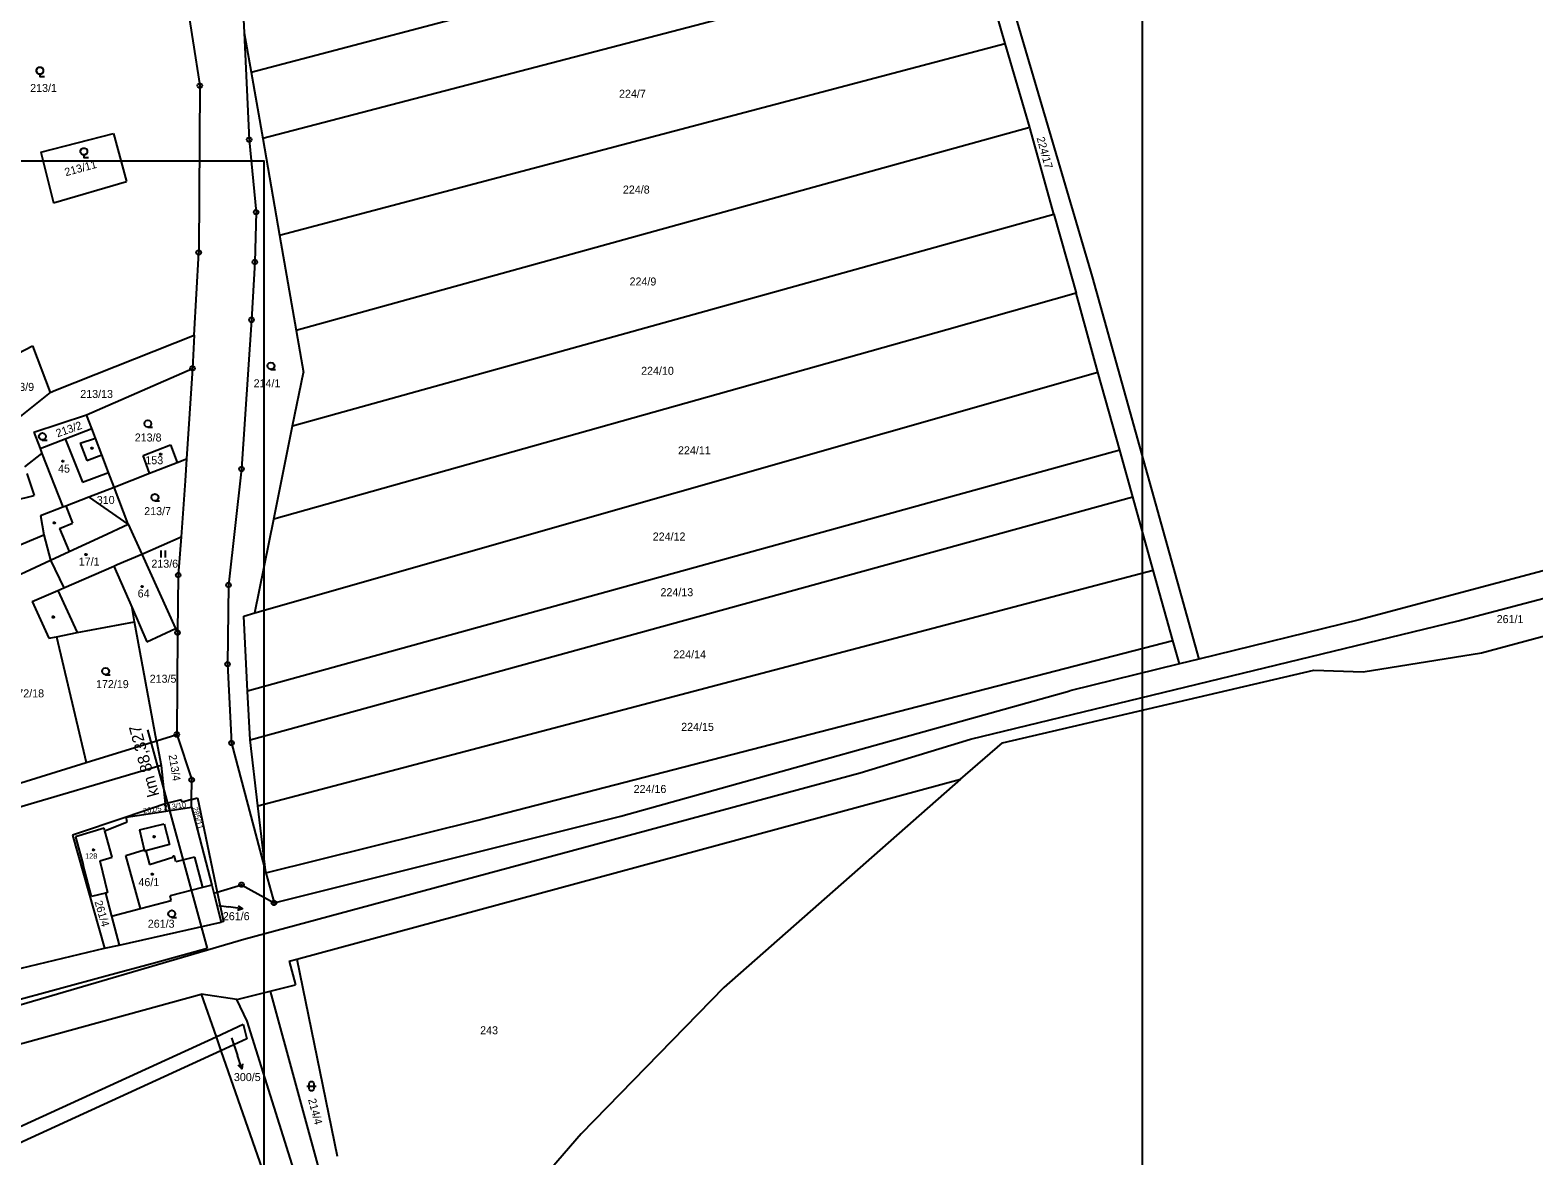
# Model space of a CAD drawing. Extents: x -780000 to -777378, y -1011169 to -1009297.
# Drawn here: x -778986.4 to -778666.9, y -1010479.3 to -1010240.1 of the extents above; entities that cross this region are included whole.
import ezdxf

# ---------------------------------------------------------------- set-up
doc = ezdxf.new("R2010")
doc.units = 0
for name, color, linetype in [('Default', 7, 'Continuous'), ('KLADY_ZMVM', 7, 'Continuous'), ('KN_HRANICE', 7, 'Continuous'), ('KN_KULTURY', 7, 'Continuous'), ('KN_PARCELY', 7, 'Continuous'), ('KN_SLUCKY', 7, 'Continuous'), ('KN_VEDENI', 7, 'Continuous'), ('LEGENDA', 7, 'Continuous'), ('staničení', 7, 'Continuous'), ('Železniční svršek', 7, 'Continuous')]:
    doc.layers.add(name, color=color, linetype=linetype)

# ---------------------------------------------------------------- blocks, each defined once
blk = doc.blocks.new('304')
at = {"layer": 'Default'}
blk.add_lwpolyline([(0, 0), (-0.38, 0.1), (-0.65, 0.37), (-0.75, 0.74), (-0.65, 1.11), (-0.38, 1.38), (-0.01, 1.48), (0.36, 1.38), (0.63, 1.11), (0.73, 0.73), (0.63, 0.35), (0.36, 0.08), (-0.02, -0.02), (0.98, -0.02)], dxfattribs=at)
blk = doc.blocks.new('305')
at = {"layer": 'Default'}
blk.add_lwpolyline([(0, 0.53), (-0.19, 0.53), (-0.53, 0.72), (-0.72, 1.06), (-0.72, 1.45), (-0.53, 1.79), (-0.19, 1.98), (0.2, 1.98), (0.54, 1.79), (0.73, 1.45), (0.73, 1.06), (0.54, 0.72), (0.2, 0.53), (0.01, 0.53), (0.01, 0), (1.01, 0)], dxfattribs=at)
blk = doc.blocks.new('306')
at = {"layer": 'Default'}
for p, q in [((-0.5, 1.5), (-0.5, 0)), ((0.5, 0), (0.5, 1.5))]:
    blk.add_line(p, q, dxfattribs=at)
blk = doc.blocks.new('316')
at = {"layer": 'Default'}
for points in [[(-1, 1), (0.27, 1), (1, 1)], [(-0.5, 1.5), (-0.4, 1.79), (-0.15, 1.97), (0.16, 1.97), (0.41, 1.79), (0.51, 1.5), (0.51, 0.5), (0.41, 0.21), (0.16, 0.03), (-0.15, 0.03), (-0.4, 0.21), (-0.5, 0.5), (-0.5, 1.5)]]:
    blk.add_lwpolyline(points, dxfattribs=at)
blk = doc.blocks.new('10292')
at = {"layer": 'Default'}
blk.add_line((0, 3), (0, 0), dxfattribs=at)
blk.add_lwpolyline([(-0.5, 2), (0, 3), (0.5, 2)], dxfattribs=at)
blk = doc.blocks.new('402')
at = {"layer": 'Default'}
blk.add_lwpolyline([(0.09, 0.15), (0.18, 0), (0.09, -0.15), (-0.09, -0.15), (-0.18, 0), (-0.09, 0.15), (0.09, 0.15)], dxfattribs=at)
blk = doc.blocks.new('105')
at = {"layer": 'Default'}
blk.add_line((-0.12, 0), (0.12, 0), dxfattribs=at)
blk.add_lwpolyline([(0.15, 0.48), (0.4, 0.3), (0.5, 0.01), (0.4, -0.28), (0.15, -0.46), (-0.16, -0.46), (-0.41, -0.28), (-0.51, 0.01), (-0.41, 0.3), (-0.16, 0.48), (0.15, 0.48)], dxfattribs=at)

msp = doc.modelspace()

# ---------------------------------------------------------------- linework, layer by layer
at = {"layer": 'KLADY_ZMVM'}
msp.add_lwpolyline([(-779108.78, -1010500), (-778750, -1010500), (-778750, -1010000)], dxfattribs=at)
at = {"layer": 'KN_HRANICE'}
for p, q in [((-778810.44, -1010123.41), (-778760.75, -1010292.49)), ((-778939.44, -1010249.05), (-778789, -1010209.36)), ((-778784.9, -1010223.38), (-778936.98, -1010263.15)), ((-778779.19, -1010242.93), (-778784.9, -1010223.38)), ((-778953.35, -1010232.46), (-778950.34, -1010251.89)), ((-778941.17, -1010234.88), (-778940.9, -1010240.67)), ((-778940.9, -1010240.67), (-778939.84, -1010263.37)), ((-778940.9, -1010240.67), (-778939.44, -1010249.05)), ((-778933.41, -1010283.65), (-778779.19, -1010242.93)), ((-778773.96, -1010260.81), (-778779.19, -1010242.93)), ((-778939.44, -1010249.05), (-778936.98, -1010263.15)), ((-778984.11, -1010266.01), (-778968.66, -1010262.03)), ((-778968.66, -1010262.03), (-778965.93, -1010272.29)), ((-778773.96, -1010260.81), (-778929.88, -1010303.92)), ((-778773.89, -1010261.06), (-778773.96, -1010260.81)), ((-778768.84, -1010279.18), (-778773.89, -1010261.06)), ((-778939.84, -1010263.37), (-778938.39, -1010278.77)), ((-778936.98, -1010263.15), (-778933.41, -1010283.65)), ((-778984.11, -1010266.01), (-778981.47, -1010276.78)), ((-778981.47, -1010276.78), (-778965.93, -1010272.29)), ((-778938.39, -1010278.77), (-778938.64, -1010289.39)), ((-778930.63, -1010324.14), (-778768.84, -1010279.18)), ((-778768.84, -1010279.18), (-778764.72, -1010293.95)), ((-778933.41, -1010283.65), (-778929.88, -1010303.92)), ((-778951.52, -1010304.9), (-778950.58, -1010287.37)), ((-778938.64, -1010289.39), (-778939.36, -1010301.65)), ((-778764.72, -1010293.95), (-778764.15, -1010296.01)), ((-778760.75, -1010292.49), (-778738.09, -1010373.73)), ((-778764.15, -1010296.01), (-778791.6, -1010303.74)), ((-778759.49, -1010312.74), (-778764.15, -1010296.01)), ((-778939.36, -1010301.65), (-778941.47, -1010333.34)), ((-778980.98, -1010316.61), (-778951.52, -1010304.9)), ((-778951.52, -1010304.9), (-778951.89, -1010311.98)), ((-778791.6, -1010303.74), (-778934.65, -1010344)), ((-778929.88, -1010303.92), (-778928.34, -1010312.81)), ((-778994.79, -1010311.83), (-778985.9, -1010307.16)), ((-778985.9, -1010307.16), (-778982.17, -1010317.08)), ((-778974.4, -1010321.81), (-778951.89, -1010311.98)), ((-778951.89, -1010311.98), (-778953.14, -1010331.19)), ((-778938.68, -1010363.9), (-778759.49, -1010312.74)), ((-778930.63, -1010324.14), (-778928.34, -1010312.81)), ((-778754.87, -1010329.33), (-778759.49, -1010312.74)), ((-778982.17, -1010317.08), (-778991.02, -1010324.17)), ((-778982.17, -1010317.08), (-778980.98, -1010316.61)), ((-778985.64, -1010325.53), (-778974.4, -1010321.81)), ((-778973.3, -1010324.71), (-778974.4, -1010321.81)), ((-778985.64, -1010325.53), (-778984.3, -1010328.99)), ((-778978.98, -1010326.92), (-778973.3, -1010324.71)), ((-778972.52, -1010326.77), (-778973.3, -1010324.71)), ((-778934.65, -1010344), (-778930.63, -1010324.14)), ((-778984.3, -1010328.99), (-778978.98, -1010326.92)), ((-778984.3, -1010328.99), (-778983.88, -1010330.06)), ((-778971.16, -1010330.34), (-778972.52, -1010326.77)), ((-778962.38, -1010330.47), (-778956.54, -1010328.23)), ((-778956.54, -1010328.23), (-778955.13, -1010331.96)), ((-778987.54, -1010332.88), (-778983.88, -1010330.06)), ((-778983.88, -1010330.06), (-778979.48, -1010341.4)), ((-778969.74, -1010334.07), (-778971.16, -1010330.34)), ((-778961.01, -1010334.24), (-778962.38, -1010330.47)), ((-778961.01, -1010334.24), (-778955.13, -1010331.96)), ((-778955.13, -1010331.96), (-778953.14, -1010331.19)), ((-778953.14, -1010331.19), (-778953.44, -1010335.87)), ((-778754.87, -1010329.33), (-778940.18, -1010380.55)), ((-778752.11, -1010339.25), (-778754.87, -1010329.33)), ((-778968.56, -1010337.17), (-778969.74, -1010334.07)), ((-778968.56, -1010337.17), (-778961.01, -1010334.24)), ((-778941.47, -1010333.34), (-778944.25, -1010358.02)), ((-778973.94, -1010339.25), (-778968.56, -1010337.17)), ((-778965.56, -1010345.08), (-778968.56, -1010337.17)), ((-778953.44, -1010335.87), (-778954.32, -1010347.77)), ((-778984.19, -1010343.23), (-778979.48, -1010341.4)), ((-778979.48, -1010341.4), (-778978.84, -1010341.15)), ((-778978.84, -1010341.15), (-778977.19, -1010340.51)), ((-778977.19, -1010340.51), (-778973.94, -1010339.25)), ((-778965.56, -1010345.08), (-778973.94, -1010339.25)), ((-778939.67, -1010390.9), (-778752.11, -1010339.25)), ((-778747.77, -1010354.85), (-778752.11, -1010339.25)), ((-778984.19, -1010343.23), (-778983.47, -1010347.31)), ((-778965.56, -1010345.08), (-778962.69, -1010351.41)), ((-778938.68, -1010363.9), (-778934.65, -1010344)), ((-778983.47, -1010347.31), (-778982.04, -1010352.73)), ((-778962.69, -1010351.41), (-778954.32, -1010347.77)), ((-778954.32, -1010347.77), (-778954.92, -1010355.9)), ((-778967.89, -1010353.67), (-778962.69, -1010351.41)), ((-778962.69, -1010351.41), (-778955.49, -1010367.27)), ((-778650.77, -1010351.2), (-778703.98, -1010365.37)), ((-778997.87, -1010360.08), (-778982.04, -1010352.73)), ((-778982.04, -1010352.73), (-778979.24, -1010358.61)), ((-778979.24, -1010358.61), (-778968.59, -1010353.97)), ((-778968.59, -1010353.97), (-778967.89, -1010353.67)), ((-778954.92, -1010355.9), (-778955.1, -1010368.13)), ((-778937.98, -1010404.92), (-778747.77, -1010354.85)), ((-778743.6, -1010369.82), (-778747.77, -1010354.85)), ((-778985.96, -1010361.53), (-778980.51, -1010359.16)), ((-778980.51, -1010359.16), (-778979.24, -1010358.61)), ((-778944.25, -1010358.02), (-778944.43, -1010374.8)), ((-778985.96, -1010361.53), (-778982.41, -1010369.32)), ((-778964.75, -1010362.86), (-778961.63, -1010370.1)), ((-778964.2, -1010365.84), (-778964.75, -1010362.86)), ((-778940.96, -1010364.6), (-778938.68, -1010363.9)), ((-778976.43, -1010368.12), (-778964.2, -1010365.84)), ((-778959.52, -1010391.1), (-778964.2, -1010365.84)), ((-778961.63, -1010370.1), (-778955.49, -1010367.27)), ((-778955.49, -1010367.27), (-778955.1, -1010368.13)), ((-778940.18, -1010380.55), (-778940.96, -1010364.6)), ((-778703.98, -1010365.37), (-778738.09, -1010373.73)), ((-778678, -1010372.43), (-778652.28, -1010365.5)), ((-778982.41, -1010369.32), (-778980.82, -1010369)), ((-778980.82, -1010369), (-778976.43, -1010368.12)), ((-778980.82, -1010369), (-778974.46, -1010395.73)), ((-778955.1, -1010368.13), (-778955.22, -1010389.77)), ((-778891.25, -1010407.94), (-778743.6, -1010369.82)), ((-778742.19, -1010374.76), (-778743.6, -1010369.82)), ((-778738.09, -1010373.73), (-778742.19, -1010374.76)), ((-778703.11, -1010376.44), (-778678, -1010372.43)), ((-778944.43, -1010374.8), (-778943.59, -1010391.58)), ((-778779.77, -1010391.5), (-778713.61, -1010376.07)), ((-778742.19, -1010374.76), (-778765.47, -1010380.48)), ((-778713.61, -1010376.07), (-778703.11, -1010376.44)), ((-778939.67, -1010390.9), (-778940.18, -1010380.55)), ((-778860.91, -1010407.13), (-778765.47, -1010380.48)), ((-778959.52, -1010391.1), (-778955.22, -1010389.77)), ((-778955.22, -1010389.77), (-778952.07, -1010399.39)), ((-778974.46, -1010395.73), (-778959.52, -1010391.1)), ((-778959.52, -1010391.1), (-778958.54, -1010396.31)), ((-778943.59, -1010391.58), (-778936.31, -1010419.18)), ((-778937.98, -1010404.92), (-778939.67, -1010390.9)), ((-778788.69, -1010399.25), (-778779.77, -1010391.5)), ((-778988.37, -1010400.03), (-778974.46, -1010395.73)), ((-778958.54, -1010396.31), (-779043.02, -1010421.24)), ((-778958.54, -1010396.31), (-778957.7, -1010404.52)), ((-778952.08, -1010403.6), (-778952.07, -1010399.39)), ((-778929.7, -1010437.49), (-778788.69, -1010399.25)), ((-778788.69, -1010399.25), (-778838.99, -1010443.52)), ((-778957.7, -1010404.52), (-778966, -1010407.32)), ((-778954.34, -1010403.64), (-778957.7, -1010404.52)), ((-778957.7, -1010404.52), (-778957.55, -1010406.02)), ((-778957.55, -1010406.02), (-778952.09, -1010405.18)), ((-778954.03, -1010404.17), (-778954.34, -1010403.64)), ((-778952.08, -1010403.6), (-778954.03, -1010404.17)), ((-778952.09, -1010405.18), (-778952.08, -1010403.6)), ((-778952.09, -1010405.18), (-778947.8, -1010421.79)), ((-778952.08, -1010403.6), (-778950.86, -1010403.24)), ((-778950.86, -1010403.24), (-778946.64, -1010423.24)), ((-778936.31, -1010419.18), (-778937.98, -1010404.92)), ((-778966, -1010407.32), (-778977.43, -1010411.17)), ((-778970.52, -1010410.2), (-778965.76, -1010408.34)), ((-778966, -1010407.32), (-778957.55, -1010406.02)), ((-778965.76, -1010408.34), (-778966, -1010407.32)), ((-778936.31, -1010419.18), (-778891.25, -1010407.94)), ((-778934.57, -1010425.53), (-778860.91, -1010407.13)), ((-778977.43, -1010411.17), (-778970.59, -1010435.19)), ((-778970.66, -1010409.66), (-778976.79, -1010411.48)), ((-778976.79, -1010411.48), (-778975.16, -1010417.48)), ((-778970.52, -1010410.2), (-778970.66, -1010409.66)), ((-778968.98, -1010415.79), (-778970.52, -1010410.2)), ((-778973.38, -1010424.16), (-778975.16, -1010417.48)), ((-778971.61, -1010416.57), (-778968.98, -1010415.79)), ((-778971.61, -1010416.57), (-778969.93, -1010423.36)), ((-778947.8, -1010421.79), (-778949.74, -1010422.28)), ((-778947.8, -1010421.79), (-778947.37, -1010423.47)), ((-778946.64, -1010423.24), (-778941.48, -1010421.68)), ((-778941.48, -1010421.68), (-778934.57, -1010425.53)), ((-778936.31, -1010419.18), (-778934.57, -1010425.53)), ((-778970.41, -1010423.47), (-778973.38, -1010424.16)), ((-778969.93, -1010423.36), (-778970.41, -1010423.47)), ((-778970.41, -1010423.47), (-778969.13, -1010428.34)), ((-778962.94, -1010426.72), (-778956.41, -1010425.01)), ((-778949.74, -1010422.28), (-778956.63, -1010424.04)), ((-778956.41, -1010425.01), (-778956.63, -1010424.04)), ((-778947.37, -1010423.47), (-778946.64, -1010423.24)), ((-778947.37, -1010423.47), (-778945.78, -1010429.62)), ((-778946.64, -1010423.24), (-778945.31, -1010429.51)), ((-778969.13, -1010428.34), (-778962.94, -1010426.72)), ((-778969.13, -1010428.34), (-778967.51, -1010434.5)), ((-778967.51, -1010434.5), (-778945.78, -1010429.62)), ((-778945.31, -1010429.51), (-778945.78, -1010429.62)), ((-778970.59, -1010435.19), (-778967.51, -1010434.5)), ((-779030.17, -1010449.35), (-778970.59, -1010435.19)), ((-778931.37, -1010437.94), (-778929.7, -1010437.49)), ((-778929.7, -1010437.49), (-778921.17, -1010479.33)), ((-778931.37, -1010437.94), (-778930.03, -1010442.98)), ((-778935.36, -1010444.3), (-778930.03, -1010442.98)), ((-778838.99, -1010443.52), (-778869.31, -1010474.62)), ((-779027.37, -1010466.13), (-778950.06, -1010444.91)), ((-778942.45, -1010446.06), (-778950.06, -1010444.91)), ((-778950.06, -1010444.91), (-778946.9, -1010453.97)), ((-778942.45, -1010446.06), (-778935.36, -1010444.3)), ((-778940.29, -1010450.68), (-778942.45, -1010446.06)), ((-778935.36, -1010444.3), (-778923.56, -1010487.7)), ((-778946.9, -1010453.97), (-778941.12, -1010451.33)), ((-778941.12, -1010451.33), (-778940.34, -1010454.4)), ((-778929.57, -1010484.72), (-778940.29, -1010450.68)), ((-778945.86, -1010456.94), (-778990.5, -1010477.42)), ((-778990.37, -1010473.89), (-778946.9, -1010453.97)), ((-778946.9, -1010453.97), (-778945.86, -1010456.94)), ((-778940.34, -1010454.4), (-778945.86, -1010456.94)), ((-778945.86, -1010456.94), (-778927.24, -1010510.3)), ((-778869.31, -1010474.62), (-778908.34, -1010519.61))]:
    msp.add_line(p, q, dxfattribs=at)
msp.add_lwpolyline([(-778950.34, -1010251.89), (-778950.58, -1010286.9), (-778950.58, -1010287.37)], dxfattribs=at)
at = {"layer": 'KN_PARCELY'}
for p, q in [((-778946.3, -1010426.12), (-778944.25, -1010426.4)), ((-778943.64, -1010454.24), (-778942.37, -1010457.97))]:
    msp.add_line(p, q, dxfattribs=at)
at = {"layer": 'KN_SLUCKY'}
for p, q in [((-778978.98, -1010326.92), (-778975.29, -1010336.14)), ((-778975.77, -1010327.87), (-778972.52, -1010326.77)), ((-778975.77, -1010327.87), (-778974.32, -1010331.52)), ((-778974.32, -1010331.52), (-778971.16, -1010330.34)), ((-778987.09, -1010334.27), (-778985.56, -1010339)), ((-778975.29, -1010336.14), (-778969.74, -1010334.07)), ((-778996.79, -1010341.72), (-778985.56, -1010339)), ((-778978.84, -1010341.15), (-778977.42, -1010344.84)), ((-778980.14, -1010345.98), (-778977.42, -1010344.84)), ((-778970.99, -1010347.6), (-778965.56, -1010345.08)), ((-779000.55, -1010354.53), (-778983.47, -1010347.31)), ((-778980.14, -1010345.98), (-778978.1, -1010350.9)), ((-778978.1, -1010350.9), (-778970.99, -1010347.6)), ((-778982.04, -1010352.73), (-778978.1, -1010350.9)), ((-778968.59, -1010353.97), (-778964.75, -1010362.86)), ((-778980.51, -1010359.16), (-778976.43, -1010368.12)), ((-778963.18, -1010410.04), (-778957.95, -1010408.71)), ((-778957.95, -1010408.71), (-778956.78, -1010413.11)), ((-778963.18, -1010410.04), (-778962.15, -1010414.29)), ((-778966.1, -1010415.49), (-778962.15, -1010414.29)), ((-778962.15, -1010414.29), (-778962.09, -1010414.54)), ((-778962.09, -1010414.54), (-778961.8, -1010414.46)), ((-778956.78, -1010413.11), (-778961.8, -1010414.46)), ((-778961.8, -1010414.46), (-778961.07, -1010417.35)), ((-778962.94, -1010426.72), (-778966.1, -1010415.49)), ((-778961.07, -1010417.35), (-778956.08, -1010415.8)), ((-778955.71, -1010415.59), (-778956.1, -1010415.63)), ((-778956.1, -1010415.63), (-778956.08, -1010415.8)), ((-778955.41, -1010416.79), (-778955.71, -1010415.59)), ((-778951.46, -1010415.8), (-778955.41, -1010416.79)), ((-778951.46, -1010415.8), (-778949.74, -1010422.28))]:
    msp.add_line(p, q, dxfattribs=at)
at = {"layer": 'KN_VEDENI'}
for p, q in [((-778682.94, -1010365.64), (-778610.59, -1010346.52)), ((-778786.59, -1010390.75), (-778682.94, -1010365.64)), ((-778810.01, -1010397.92), (-778786.59, -1010390.75)), ((-778940.99, -1010433.26), (-778810.01, -1010397.92)), ((-779042.85, -1010463.08), (-778940.99, -1010433.26))]:
    msp.add_line(p, q, dxfattribs=at)
at = {"layer": 'LEGENDA'}
msp.add_lwpolyline([(-779530.66, -1010687.91), (-778936.66, -1010687.91), (-778936.66, -1010267.91), (-779530.66, -1010267.91)], close=True, dxfattribs=at)
at = {"layer": 'staničení'}
msp.add_line((-778961.48, -1010388.77), (-778948.81, -1010435.26), dxfattribs=at)
at = {"layer": 'Železniční svršek'}
for points in [[(-778948.81, -1010435.26), (-778959.77, -1010438.24)], [(-778970.05, -1010441.03), (-778980.42, -1010443.86)], [(-778959.77, -1010438.25), (-778970.04, -1010441.03)], [(-778980.43, -1010443.86), (-778990.86, -1010446.68)]]:
    msp.add_lwpolyline(points, dxfattribs=at)
for centre, start, end in [((-778969.78, -1010441.99), 105.1631, 105.2607), ((-778960.03, -1010437.28), 285.1631, 285.241), ((-778980.69, -1010442.9), 285.1366, 285.2607)]:
    msp.add_arc(centre, 1, start, end, dxfattribs=at)

# ---------------------------------------------------------------- block references
at = {"layer": 'KN_KULTURY'}
for name, p in [('305', (-778984.34, -1010249.95)), ('305', (-778974.98, -1010267.13)), ('304', (-778935.21, -1010312.17)), ('304', (-778983.79, -1010327.17)), ('304', (-778961.38, -1010324.45)), ('402', (-778973.25, -1010328.93)), ('402', (-778979.46, -1010331.7)), ('402', (-778958.66, -1010330.2)), ('304', (-778959.86, -1010340.11)), ('402', (-778981.27, -1010344.78)), ('402', (-778974.54, -1010351.5)), ('306', (-778958.14, -1010352.14)), ('402', (-778962.61, -1010358.29)), ('402', (-778981.46, -1010364.79)), ('304', (-778970.35, -1010377.05)), ('402', (-778960.04, -1010411.46)), ('402', (-778972.93, -1010414.29)), ('402', (-778960.42, -1010419.46)), ('304', (-778956.29, -1010428.59)), ('316', (-778926.63, -1010465.47))]:
    msp.add_blockref(name, p, dxfattribs=at)
at = {"layer": 'KN_PARCELY'}
for p in [(-778950.34, -1010251.89), (-778939.84, -1010263.37), (-778938.39, -1010278.77), (-778950.58, -1010287.37), (-778938.64, -1010289.39), (-778939.36, -1010301.65), (-778951.89, -1010311.98), (-778941.47, -1010333.34), (-778954.92, -1010355.9), (-778944.25, -1010358.02), (-778955.1, -1010368.13), (-778944.43, -1010374.8), (-778955.22, -1010389.77), (-778943.59, -1010391.58), (-778952.07, -1010399.39), (-778941.48, -1010421.68), (-778934.57, -1010425.53)]:
    msp.add_blockref('105', p, dxfattribs=at)
for p, rotation in [((-778944.25, -1010426.4), -97.64262599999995), ((-778942.37, -1010457.97), -161.183645)]:
    msp.add_blockref('10292', p, dxfattribs=dict(at, rotation=rotation))

# ---------------------------------------------------------------- texts
for s, height, p in [('213/1', 1.7, (-778986.39, -1010253.23)), ('224/7', 1.7, (-778861.26, -1010254.46)), ('224/8', 1.7, (-778860.44, -1010274.82)), ('224/9', 1.7, (-778859.02, -1010294.35)), ('224/10', 1.7, (-778856.57, -1010313.33)), ('213/9', 1.7, (-778991.25, -1010316.75)), ('214/1', 1.7, (-778938.91, -1010315.98)), ('213/13', 1.7, (-778975.75, -1010318.25)), ('213/8', 1.7, (-778964.17, -1010327.5)), ('224/11', 1.7, (-778848.73, -1010330.23)), ('153', 1.7, (-778961.92, -1010332.33)), ('45', 1.7, (-778980.46, -1010334.11)), ('310', 1.7, (-778972.24, -1010340.78)), ('213/7', 1.7, (-778962.16, -1010343.15)), ('224/12', 1.7, (-778854.1, -1010348.54)), ('17/1', 1.7, (-778976.06, -1010353.85)), ('213/6', 1.7, (-778960.64, -1010354.31)), ('64', 1.7, (-778963.55, -1010360.64)), ('224/13', 1.7, (-778852.45, -1010360.37)), ('261/1', 1.7, (-778674.77, -1010366.09)), ('224/14', 1.7, (-778849.74, -1010373.58)), ('213/5', 1.7, (-778961, -1010378.76)), ('172/18', 1.7, (-778990.39, -1010381.87)), ('172/19', 1.7, (-778972.4, -1010379.9)), ('224/15', 1.7, (-778848.05, -1010388.98)), ('224/16', 1.7, (-778858.16, -1010402.18)), ('128', 1.14, (-778974.74, -1010416.16)), ('46/1', 1.7, (-778963.39, -1010421.98)), ('261/6', 0.1, (-778946.54, -1010426.12)), ('261/6', 1.7, (-778945.45, -1010429.21)), ('261/3', 1.7, (-778961.4, -1010430.81)), ('243', 1.7, (-778890.77, -1010453.45)), ('300/5', 0.1, (-778943.63, -1010454.24)), ('300/5', 1.7, (-778943.1, -1010463.4))]:
    msp.add_text(s, height=height, dxfattribs=at).set_placement(p)
for s, height, rotation, p in [('224/17', 1.7, 285.562, (-778772.55, -1010263.01)), ('213/11', 1.7, 15.298, (-778978.81, -1010271.15)), ('213/2', 1.7, 19.309, (-778980.58, -1010326.63)), ('213/4', 1.7, 279.374, (-778956.98, -1010394.15)), ('261/5', 1.14, 7.964, (-778962.33, -1010406.55)), ('213/10', 1.14, 7.62, (-778957.97, -1010405.86)), ('285/11', 1.14, 284.932, (-778951.91, -1010405.34)), ('261/4', 1.7, 286.364, (-778972.74, -1010425.31)), ('214/4', 1.7, 285.047, (-778927.36, -1010467.32))]:
    msp.add_text(s, height=height, rotation=rotation, dxfattribs=at).set_placement(p)
at = {"layer": 'staničení'}
msp.add_text('km 88,327', height=2.5, rotation=105.241, dxfattribs=at).set_placement((-778958.93, -1010402.61))

doc.saveas('drawing.dxf')
